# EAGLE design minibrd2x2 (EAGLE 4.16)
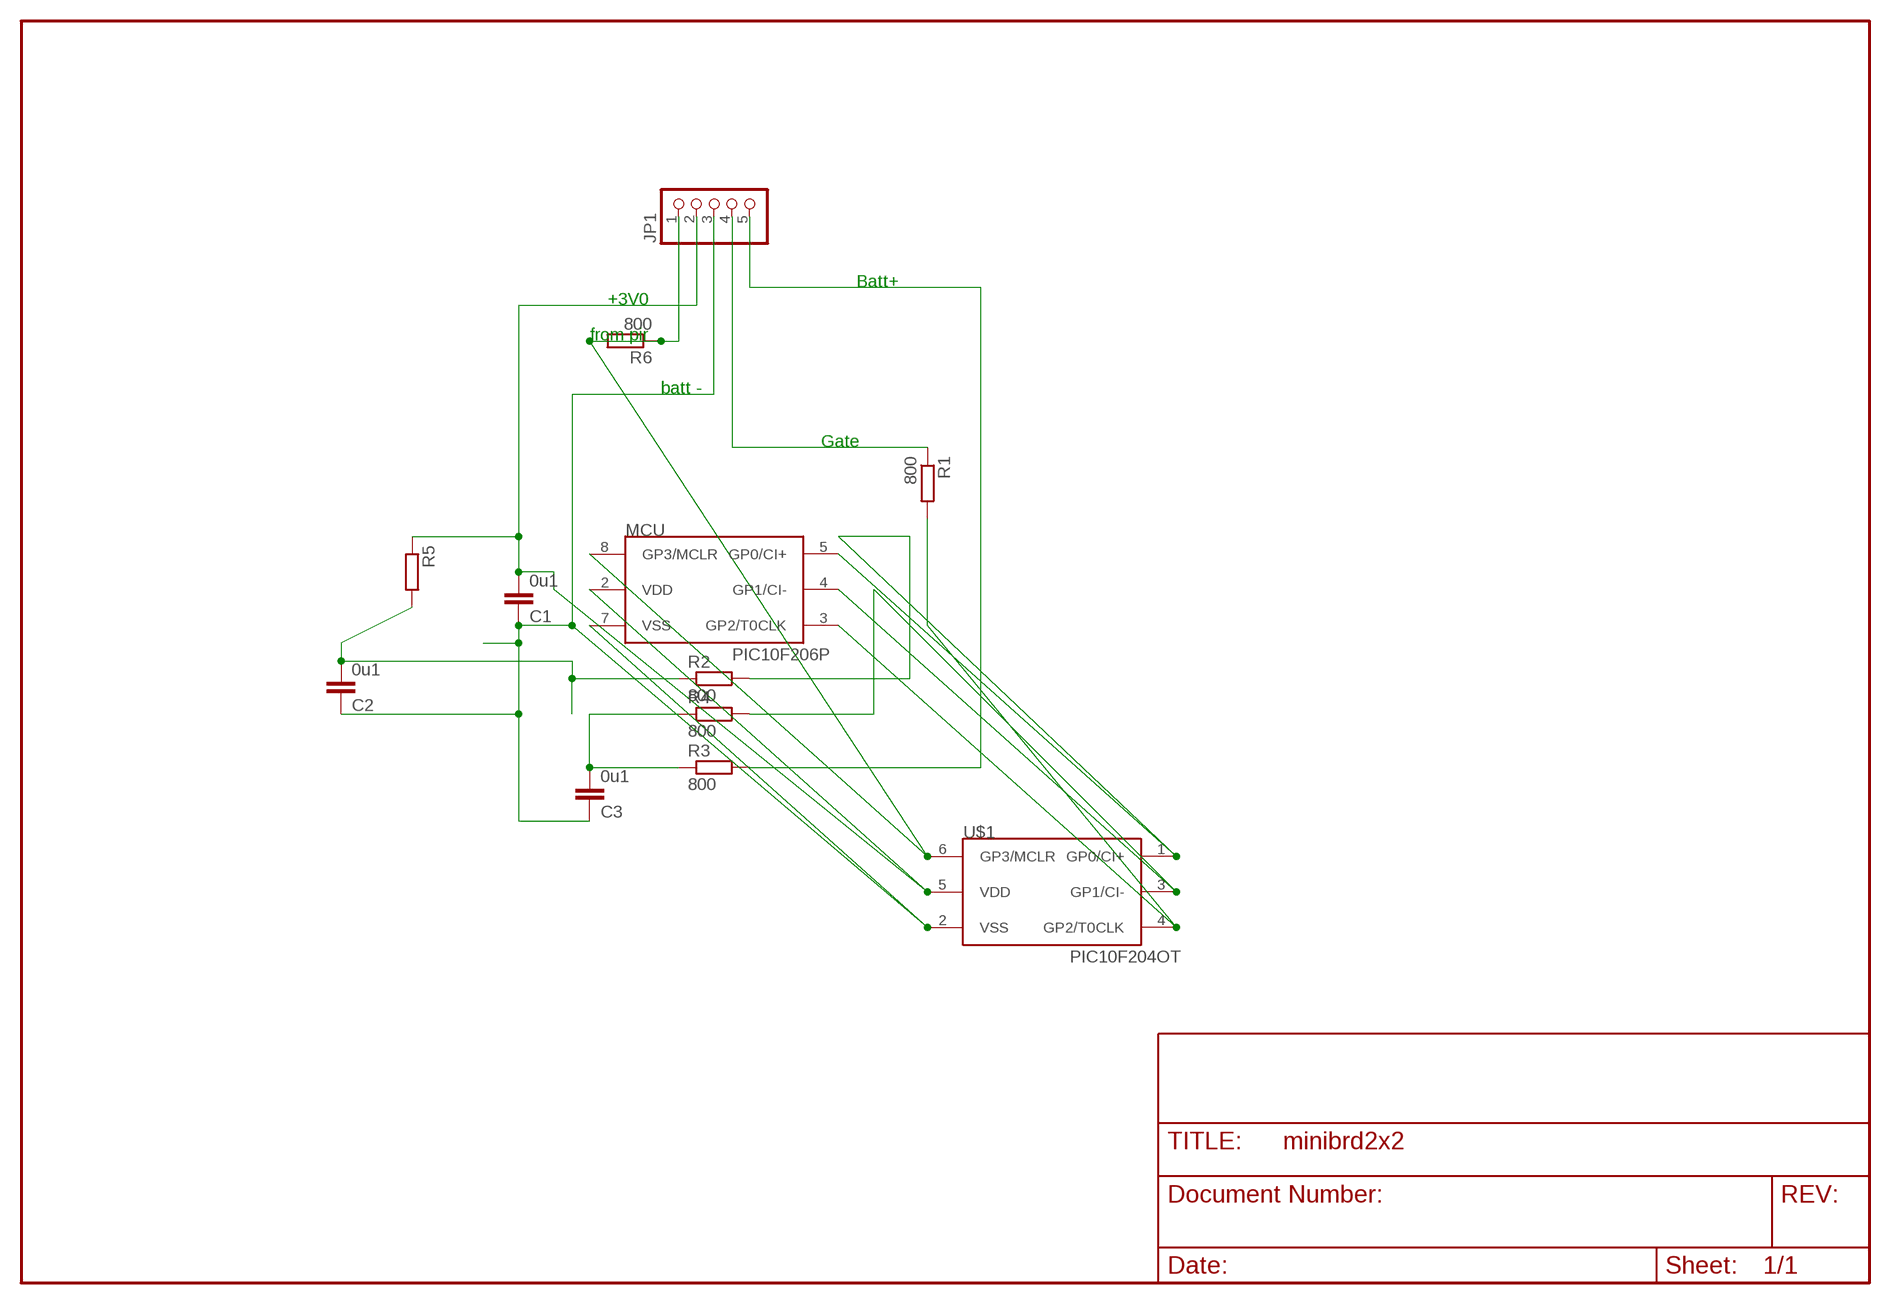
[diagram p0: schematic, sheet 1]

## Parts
C1  0u1  C-EUC1206  [C1206]
C2  0u1  C-EUC1206  [C1206]
C3  0u1  C-EUC1206  [C1206]
JP1  PINHD-1X5  [1X05]
MCU  PIC10F206P  [DIL8]
R1  800  R-EU_R1206  [R1206]
R2  800  R-EU_R1206  [R1206]
R3  800  R-EU_R1206  [R1206]
R4  800  R-EU_R1206  [R1206]
R5  R-EU_0613/5V  [P0613V]
R6  800  R-EU_R1206  [R1206]
U$1  PIC10F204OT  [SOT23-6]

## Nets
GATE: JP1.4 R1.1
N$1: C2.2 R2.1 R5.2
N$4: MCU.5(GP0/CI+) R2.2 U$1.1(GP0/CI+)
N$5: MCU.3(GP2/T0CLK) R1.2 U$1.4(GP2/T0CLK)
N$7: C3.2 R3.1 R4.1
N$8: MCU.4(GP1/CI-) R4.2 U$1.3(GP1/CI-)
PIR: JP1.1 MCU.8(GP3/MCLR) R6.1 R6.2 U$1.6(GP3/MCLR)
V3: C1.2 JP1.2 MCU.2(VDD) R5.1 U$1.5(VDD)
V+: JP1.5 R3.2
V-: C1.1 C2.1 C3.1 JP1.3 MCU.7(VSS) U$1.2(VSS)

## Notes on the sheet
- Batt+
- +3V0
- from pir
- batt -
- Gate

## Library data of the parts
C1-C3 = rcl:C-EU: CAPACITOR, European symbol
JP1 = pinhead:PINHD-1X5: PIN HEADER
MCU U$1 = microchip-3:PIC10F2*: uPC nW 0,25/0,5k Program Flash memory Comparator
R1-R6 = rcl:R-EU_: RESISTOR, European symbol

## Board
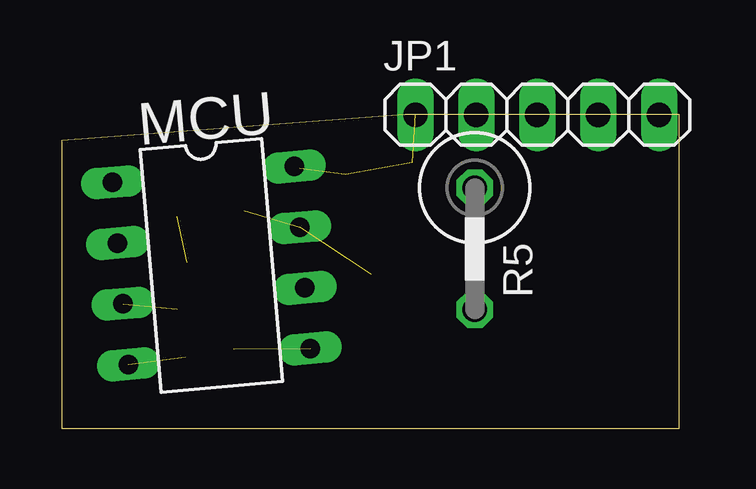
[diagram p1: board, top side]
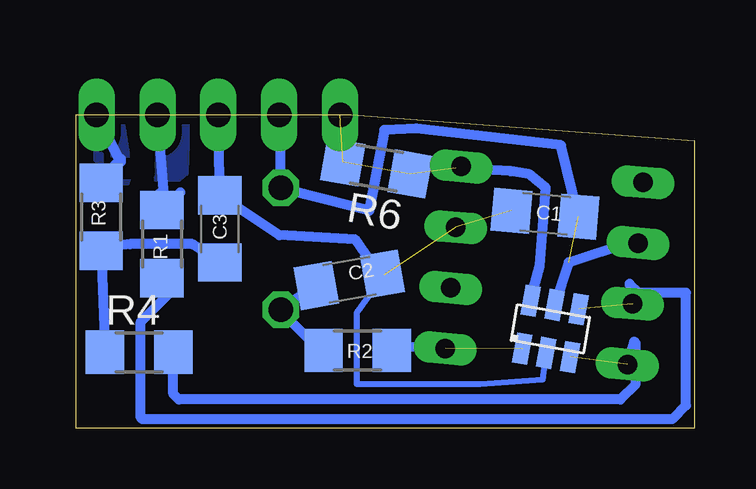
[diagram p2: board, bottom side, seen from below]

Size 25.77 x 13.08 mm. Coordinates in mm from the lower left corner, seen from the top.
Outline: 0,0 25.77,0 25.77,13.07 18,13.07 14.31,13.08 0,11.99 0,0
Copper layers (1*16): Top 0.035mm / dielectric 1.5mm / Bottom 0.035mm
Design rules "default": minimum track width 10mil, minimum drill 24mil, track to track 8mil, track to pad 8mil, pad to pad 8mil, via to via 8mil, smd to smd 8mil, copper to edge 1mil, drill to drill 8mil, minimum pad ring 10mil, minimum via ring 8mil, stop-mask expansion 4mil, vias tented up to drill 0mil, thermal gap 10mil

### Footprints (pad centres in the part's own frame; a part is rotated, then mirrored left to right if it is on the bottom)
C1206 = smd 1.6 x 1.8: 1 -1.4,0; 2 1.4,0
1X05 = drill 1.016 long: 1 -5.08,0; 2 -2.54,0; 3 0,0; 4 2.54,0; 5 5.08,0
DIL8 = drill 0.813 long: 1 -3.81,-3.81; 2 -1.27,-3.81; 3 1.27,-3.81; 4 3.81,-3.81; 5 3.81,3.81; 6 1.27,3.81; 7 -1.27,3.81; 8 -3.81,3.81
R1206 = smd 1.6 x 1.803: 1 -1.422,0; 2 1.422,0
P0613V = drill 1.016 octagon: 1 -2.54,0; 2 2.54,0
SOT23-6 = smd 0.635 x 1.27: 1 -1.016,-1.016; 2 0,-1.016; 3 1.016,-1.016; 4 1.016,1.016; 5 0,1.016; 6 -1.016,1.016

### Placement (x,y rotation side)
C1  6.22,8.95 355 bottom
C2  14.37,6.19 190 bottom
C3  19.77,8.31 270 bottom
JP1  19.84,13.08 0 top
MCU  6.25,6.79 275 top
R1  22.19,7.68 270 bottom
R2  14.03,3.25 0 bottom
R3  24.73,8.82 90 bottom
R4  23.14,3.17 0 bottom
R5  17.23,7.49 270 top
R6  13.24,10.85 170 bottom
U$1  5.99,4.14 350 bottom

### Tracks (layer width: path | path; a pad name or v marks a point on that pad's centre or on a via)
GATE
  Bottom 0.406: 21.59,9.61 21.74,9.46 | 21.59,9.61 R1.1 22.31,9.77 22.12,9.96 JP1.4 | 21.59,9.61 21.42,9.84
  pour Bottom (isolate 0.406): 21.11,13.14 22.12,13.08 22.38,12.82 22.38,10.47 22.44,10.41 21.49,10.41 21.17,10.66
N$1
  Bottom 0.406: R2.1 15.53,3.18 17.23,4.88 R5.2 17.17,5.01 C2.2
N$4  (1 unrouted)
  Bottom 0.406: 13.03,3.31 13.04,3.3 | 13.03,3.31 R2.2 | MCU.5 12.92,3.42 13.03,3.31
N$5  (1 unrouted)
  Bottom 0.406: R1.2 21.55,5.96 23.08,4.44 23.08,0.44 23.01,0.38 0.91,0.38 0.34,0.95 0.34,5.65 2.31,5.65 2.69,6.03 MCU.3
N$7
  Bottom 0.406: R4.1 R3.1 24.92,7.49 23.52,7.68 20.92,7.68 C3.2
N$8  (1 unrouted)
  Bottom 0.406: R4.2 21.72,1.43 21.49,1.2 3.07,1.2 2.44,1.84 2.44,3.55 2.5,3.61 MCU.4
PIR  (3 unrouted)
  Bottom 0.406: U$1.6 6.44,6.79 6.19,10.03 6.88,10.6 7.65,10.73 9.93,10.85 MCU.8
V3  (1 unrouted)
  Bottom 0.406: C1.2 5.55,11.81 11.58,12.5 12.92,12.44 13.55,9.08 16.28,9.77 16.73,9.9 17.23,9.84 R5.1 17.23,12.88 17.3,12.95 JP1.2 | U$1.5 5.23,6.92 2.69,7.74 MCU.2
V+
  Bottom 0.406: 24.03,11.11 25.11,10.03 25.04,10.03 24.73,10.35 R3.2 | 24.03,11.11 23.9,11.23 | 24.03,11.11 23.96,11.04 23.9,11.11 JP1.5
  pour Bottom (isolate 0.406): 23.84,12.76 25.17,12.76 25.68,12.63 25.68,10.35 25.55,10.09 23.71,10.09 23.52,10.66
V-  (2 unrouted)
  Bottom 0.254: U$1.2 6.31,2.03 8.92,1.84 14.06,1.84 14.06,4.82 12.92,6.41 C2.1
  Bottom 0.406: JP1.3 19.84,12.88 C3.1 17.3,8.06 14.12,7.87 13.23,6.6 C2.1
